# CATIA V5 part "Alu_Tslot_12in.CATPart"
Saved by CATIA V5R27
Part number: Tslotted_12in
Revision: ANY
Definition: UNKNOWN
Nomenclature: Tslotted_12in
Source: Unknown
Bounding box of the stored display mesh (mm): x -19.056 to 19.056, y -19.056 to 19.056, z -1524 to -1216.66
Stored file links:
  \\triton.meca.polymtl.ca\usagers\zaoue\profiles\Desktop\varm_ass\structure prismatique\Alu_Tslot_12in.CATPart
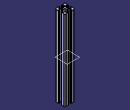
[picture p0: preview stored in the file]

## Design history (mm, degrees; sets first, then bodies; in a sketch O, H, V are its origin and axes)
Body1 "Boss-Extrude1" (main body)
  Solid1: solid without history
  Sketch1 on face of Solid1, origin (0, 0, 1524), H (1, 0, 0), V (0, 1, 0)
    line L1 (-31.855, 32.792) -> (28.107, 32.792)
    line L2 (28.107, 32.792) -> (28.107, -28.509)
    line L3 (28.107, -28.509) -> (-31.855, -28.509)
    line L4 (-31.855, -28.509) -> (-31.855, 32.792)
    horizontal: L1 H, L3 H
    vertical: L2 V, L4 V
    fix: L1, L2, L3, L4
  Pocket1: profile Sketch1, direction (0, 0, -1), length 2740.66
  Sketch2 on face of Solid1, origin (0, 0, -1524), H (1, 0, 0), V (0, -1, 0)
    line L1 (19.0564, -14.3256) -> (19.0564, -15.8623)
    arc A1 centre (19.0564, -15.0939) radius 0.7684 from (19.0564, -14.3256) to (19.0564, -15.8623) ccw
    point P3 (19.0564, -15.0939)
    line L2 (7.9756, -19.05) -> (9.4996, -19.05)
    arc A2 centre (8.7376, -19.05) radius 0.762 from (9.4996, -19.05) to (7.9756, -19.05) ccw
    point P6 (8.7376, -19.05)
    line L3 (19.05, -7.9756) -> (19.05, -9.4996)
    point P7 (19.05, -8.7376)
    arc A3 centre (19.05, -8.7376) radius 0.762 from (19.05, -7.9756) to (19.05, -9.4996) ccw
    line L4 (19.05, 9.4996) -> (19.05, 7.9756)
    point P10 (19.05, 8.7376)
    arc A4 centre (19.05, 8.7376) radius 0.762 from (19.05, 9.4996) to (19.05, 7.9756) ccw
    line L5 (19.0564, 15.8623) -> (19.0564, 14.3256)
    point P13 (19.0564, 15.0939)
    arc A5 centre (19.0564, 15.0939) radius 0.7684 from (19.0564, 15.8623) to (19.0564, 14.3256) ccw
    line L6 (-9.4996, -19.05) -> (-7.9756, -19.05)
    point P16 (-8.7376, -19.05)
    arc A6 centre (-8.7376, -19.05) radius 0.762 from (-7.9756, -19.05) to (-9.4996, -19.05) ccw
    line L7 (-15.8623, -19.0563) -> (-14.3256, -19.0563)
    point P19 (-15.0939, -19.0563)
    arc A7 centre (-15.0939, -19.0563) radius 0.7684 from (-14.3256, -19.0563) to (-15.8623, -19.0563) ccw
    line L8 (14.3256, -19.0563) -> (15.8623, -19.0563)
    point P22 (15.0939, -19.0563)
    arc A8 centre (15.0939, -19.0563) radius 0.7684 from (15.8623, -19.0563) to (14.3256, -19.0563) ccw
    reference projected arc E1 centre (19.0564, -15.0939) radius 0.7684 from (19.05, -14.3256) to (18.288, -15.0939) ccw from edge [face of Solid1 | face of Solid1]
    reference projected arc E2 centre (19.0564, -15.0939) radius 0.7684 from (19.05, -14.3256) to (18.288, -15.0939) ccw from edge [face of Solid1 | face of Solid1]
    reference projected arc E3 centre (19.05, 8.7376) radius 0.762 from (19.05, 9.4996) to (18.288, 8.7376) ccw from edge [face of Solid1 | face of Solid1]
    reference projected arc E4 centre (19.05, 8.7376) radius 0.762 from (19.05, 9.4996) to (18.288, 8.7376) ccw from edge [face of Solid1 | face of Solid1]
    reference projected arc E5 centre (19.0564, 15.0939) radius 0.7684 from (19.05, 15.8623) to (18.288, 15.0939) ccw from edge [face of Solid1 | face of Solid1]
    reference projected arc E6 centre (19.0564, 15.0939) radius 0.7684 from (19.05, 15.8623) to (18.288, 15.0939) ccw from edge [face of Solid1 | face of Solid1]
    reference projected arc E7 centre (19.05, -8.7376) radius 0.762 from (19.05, -7.9756) to (18.288, -8.7376) ccw from edge [face of Solid1 | face of Solid1]
    reference projected arc E8 centre (19.05, -8.7376) radius 0.762 from (19.05, -7.9756) to (18.288, -8.7376) ccw from edge [face of Solid1 | face of Solid1]
    reference projected arc E9 centre (15.0939, -19.0563) radius 0.7684 from (15.8623, -19.05) to (14.3256, -19.05) ccw from edge [face of Solid1 | face of Solid1]
    reference projected arc E10 centre (15.0939, -19.0563) radius 0.7684 from (15.8623, -19.05) to (14.3256, -19.05) ccw from edge [face of Solid1 | face of Solid1]
    reference projected arc E11 centre (8.7376, -19.05) radius 0.762 from (9.4996, -19.05) to (7.9756, -19.05) ccw from edge [face of Solid1 | face of Solid1]
    reference projected arc E12 centre (8.7376, -19.05) radius 0.762 from (9.4996, -19.05) to (7.9756, -19.05) ccw from edge [face of Solid1 | face of Solid1]
    reference projected arc E13 centre (-8.7376, -19.05) radius 0.762 from (-7.9756, -19.05) to (-9.4996, -19.05) ccw from edge [face of Solid1 | face of Solid1]
    reference projected arc E14 centre (-8.7376, -19.05) radius 0.762 from (-7.9756, -19.05) to (-9.4996, -19.05) ccw from edge [face of Solid1 | face of Solid1]
    reference projected arc E15 centre (-15.0939, -19.0563) radius 0.7684 from (-14.3256, -19.05) to (-15.8623, -19.05) ccw from edge [face of Solid1 | face of Solid1]
    reference projected arc E16 centre (-15.0939, -19.0563) radius 0.7684 from (-14.3256, -19.05) to (-15.8623, -19.05) ccw from edge [face of Solid1 | face of Solid1]
    vertical: L1 V, L3 V, L4 V, L5 V
    midpoint: P3 L1, P6 L2, P7 L3, P10 L4, P13 L5, P16 L6, P19 L7, P22 L8
    horizontal: L2 H, L6 H, L7 H, L8 H
    coincidence: A1 E1, A4 E3, A5 E5, A3 E7, A8 E9, A2 E11, A6 E13, A7 E15
    concentricity: A1 E2, A4 E4, A5 E6, A3 E8, A8 E10, A2 E12, A6 E14, A7 E16
  Pad1: profile Sketch2, direction (0, 0, -1), up to end face of Pocket1
  Mirror1: of Pad1, about {plane type Offset, RefPlane face of Solid1, Offset 19.05}
  Mirror2: of Pad1, about {plane type Offset, RefPlane face of Solid1, Offset 19.05}
  Plane1: type Offset, RefPlane face of Solid1, Offset 153.67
